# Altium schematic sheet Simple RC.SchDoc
size A4; Organization: Altium Limited; Address1: L3, 12a Rodborough Rd; Address2: Frenchs Forest; Address3: NSW; Address4: Australia 2086; DocumentNumber: 1; SheetNumber: 1; SheetTotal: 1
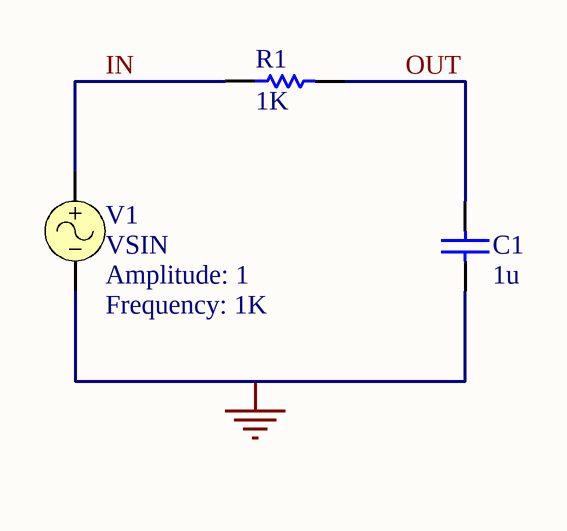
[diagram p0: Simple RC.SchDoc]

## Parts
C1  value 1u  [RAD-0.3]  (hidden comment: Cap)
R1  value 1K  [AXIAL-0.3]  (hidden comment: Res1)
V1  VSIN  Amplitude: 1  Frequency: 1K

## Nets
GND: C1.1 V1.2
IN: R1.1 V1.1
OUT: C1.2 R1.2

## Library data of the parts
C1 = Cap: Capacitor; Manufacturer: Generic Components; Class I: Passive
R1 = Res1: Resistor; Manufacturer: Generic Components; Class I: Passive
V1 = VSIN: Sinusoidal Voltage Source; Manufacturer: Generic Components; Revision 1: 15-Jun-2001: Default value added for damping factor (F8:0).; Revision 2: 17-July-2002: Re-released for DXP Platform.; Class I: Simulation; Note: PCB Footprint - Not required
